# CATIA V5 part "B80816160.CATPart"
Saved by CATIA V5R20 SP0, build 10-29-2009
Part number: B80816160
Revision: 3
Definition: design
Nomenclature: B80816160
Source: made
Description: NOT SPECIFIED
Bounding box of the stored display mesh (mm): x -10 to 10, y -10 to 10, z 0 to 160
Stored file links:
  C:\Users\Raffaele\Desktop\3D X SITO CF\BOLEX\4-PILLAR REF 808\B80816160.CATPart
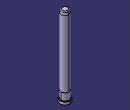
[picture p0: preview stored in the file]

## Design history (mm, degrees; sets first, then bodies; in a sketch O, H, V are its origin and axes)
Body1 "MANIFOLD_SOLID_BREP #450" (main body)
  Solid1: solid without history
